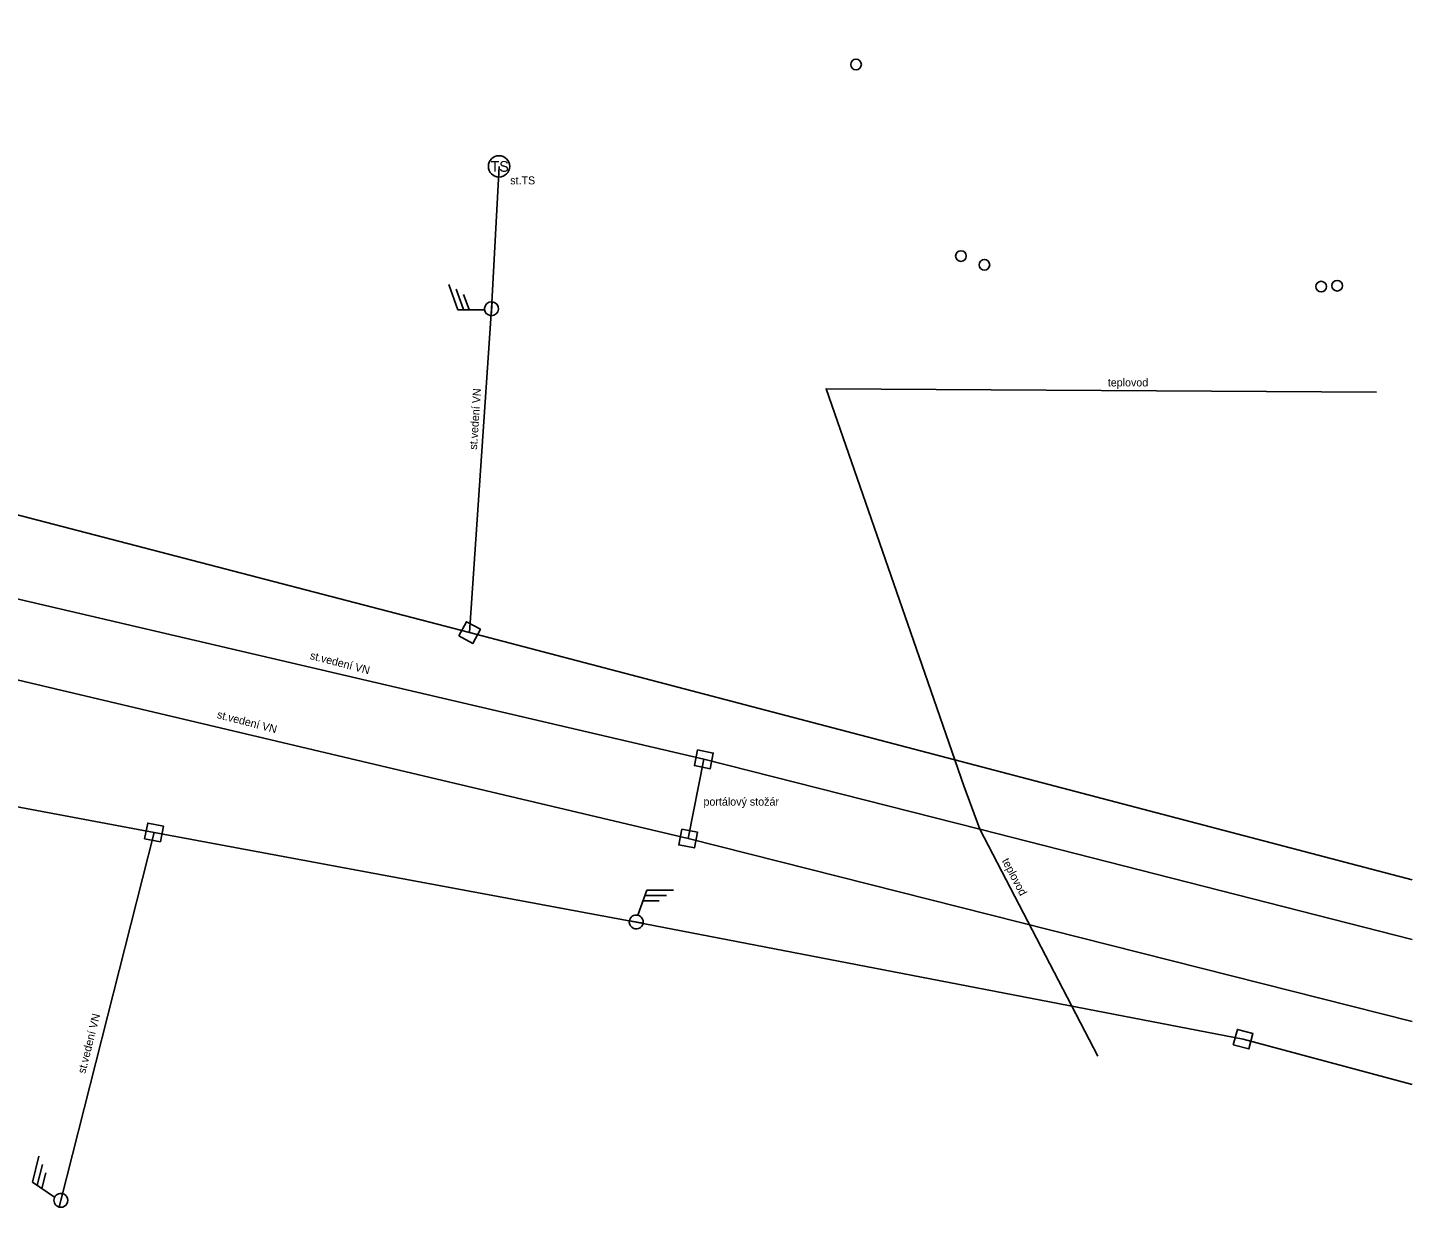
# Model space of a CAD drawing. Extents: x -763601 to -762500, y -1153000 to -1152585.
# Drawn here: x -762629.8 to -762500, y -1152813.9 to -1152703.3 of the extents above; entities that cross this region are included whole.
import ezdxf

# ---------------------------------------------------------------- set-up
doc = ezdxf.new("R2010")
doc.units = 0
for name, color, linetype in [('Vrstva 1', 7, 'Continuous'), ('Vrstva 10', 7, 'Continuous'), ('Vrstva 2', 7, 'Continuous'), ('Vrstva 9', 7, 'Continuous')]:
    doc.layers.add(name, color=color, linetype=linetype)

msp = doc.modelspace()

# ---------------------------------------------------------------- linework, layer by layer
at = {"layer": 'Vrstva 1'}
for p, q in [((-762589.451, -1152729.766), (-762590.306, -1152727.417)), ((-762588.93, -1152729.736), (-762589.614, -1152727.857)), ((-762588.392, -1152729.753), (-762588.905, -1152728.344)), ((-762586.951, -1152729.766), (-762589.451, -1152729.766)), ((-762586.246, -1152729.031), (-762586.334, -1152730.329)), ((-762572.585, -1152786.51), (-762571.73, -1152784.16)), ((-762571.88, -1152784.66), (-762569.88, -1152784.66)), ((-762571.73, -1152784.16), (-762569.23, -1152784.16)), ((-762572.08, -1152785.16), (-762570.58, -1152785.16)), ((-762572.091, -1152787.279), (-762573.369, -1152787.041)), ((-762629.313, -1152811.545), (-762628.7, -1152809.121)), ((-762628.865, -1152811.813), (-762628.374, -1152809.874)), ((-762627.245, -1152812.95), (-762629.313, -1152811.545)), ((-762628.429, -1152812.129), (-762628.061, -1152810.675)), ((-762626.493, -1152812.619), (-762626.807, -1152813.881))]:
    msp.add_line(p, q, dxfattribs=at)
for points in [[(-762829.28, -1152697.23), (-762715.88, -1152726.83), (-762588.34, -1152760.03)], [(-762585.59, -1152716.34), (-762586.29, -1152729.68), (-762588.34, -1152760.03)], [(-762746.54, -1152729.84), (-762566.39, -1152771.91)], [(-762745.34, -1152737.36), (-762567.86, -1152779.34)], [(-762877.14, -1152789.46), (-762747.36, -1152754.48), (-762617.92, -1152778.76)], [(-762588.34, -1152760.03), (-762500, -1152783.22)], [(-762567.86, -1152779.34), (-762566.39, -1152771.91)], [(-762566.39, -1152771.91), (-762540.52, -1152778.47), (-762500, -1152788.8)], [(-762617.92, -1152778.76), (-762626.65, -1152813.25)], [(-762617.92, -1152778.76), (-762572.73, -1152787.16), (-762515.86, -1152798.14), (-762500, -1152802.4)], [(-762567.86, -1152779.34), (-762500, -1152796.48)]]:
    msp.add_lwpolyline(points, dxfattribs=at)
for points in [[(-762589.354, -1152760.34), (-762588.03, -1152761.044), (-762587.326, -1152759.72), (-762588.65, -1152759.016)], [(-762566.98, -1152771.029), (-762567.271, -1152772.5), (-762565.8, -1152772.791), (-762565.509, -1152771.32)], [(-762618.799, -1152779.353), (-762617.327, -1152779.639), (-762617.041, -1152778.167), (-762618.513, -1152777.881)], [(-762568.45, -1152778.459), (-762568.741, -1152779.93), (-762567.27, -1152780.221), (-762566.979, -1152778.75)], [(-762516.779, -1152798.67), (-762515.33, -1152799.059), (-762514.941, -1152797.61), (-762516.39, -1152797.221)]]:
    msp.add_lwpolyline(points, close=True, dxfattribs=at)
msp.add_circle((-762585.59, -1152716.34), 1, dxfattribs=at)
for centre, start, end in [((-762586.29, -1152729.68), 86.13801, 266.13801), ((-762586.29, -1152729.68), 266.13801, 86.13801), ((-762572.73, -1152787.16), 169.46983, 349.46983), ((-762572.73, -1152787.16), 349.46983, 169.46983), ((-762626.65, -1152813.25), 76.00012, 256.00012), ((-762626.65, -1152813.25), 256.00012, 76.00012)]:
    msp.add_arc(centre, 0.65, start, end, dxfattribs=at)
at = {"layer": 'Vrstva 9'}
msp.add_lwpolyline([(-762503.37, -1152737.5), (-762554.94, -1152737.17), (-762546.21, -1152762.3), (-762542.04, -1152774.39), (-762540.52, -1152778.47), (-762529.46, -1152799.72)], dxfattribs=at)
for centre in [(-762552.13, -1152706.78), (-762542.3, -1152724.74), (-762540.1, -1152725.56), (-762508.54, -1152727.6), (-762507.04, -1152727.52)]:
    msp.add_circle(centre, 0.5, dxfattribs=at)

# ---------------------------------------------------------------- texts
at = {"layer": 'Vrstva 1'}
msp.add_text('TS', height=1, dxfattribs=at).set_placement((-762586.383, -1152716.84))
at = {"layer": 'Vrstva 10'}
msp.add_text('teplovod', height=0.75, dxfattribs=at).set_placement((-762528.54, -1152736.96))
msp.add_text('teplovod', height=0.75, rotation=297.49644, dxfattribs=at).set_placement((-762538.48, -1152781.41))
at = {"layer": 'Vrstva 2'}
for s, p in [('st.TS', (-762584.54, -1152718.02)), ('portálový stožár', (-762566.43, -1152776.25))]:
    msp.add_text(s, height=0.75, dxfattribs=at).set_placement(p)
for rotation, p in [(86.13581, (-762587.66, -1152742.9)), (345.39113, (-762603.36, -1152762.5)), (345.39113, (-762612.07, -1152768.03)), (75.7958, (-762624.37, -1152801.42))]:
    msp.add_text('st.vedení VN', height=0.75, rotation=rotation, dxfattribs=at).set_placement(p)

doc.saveas('drawing.dxf')
